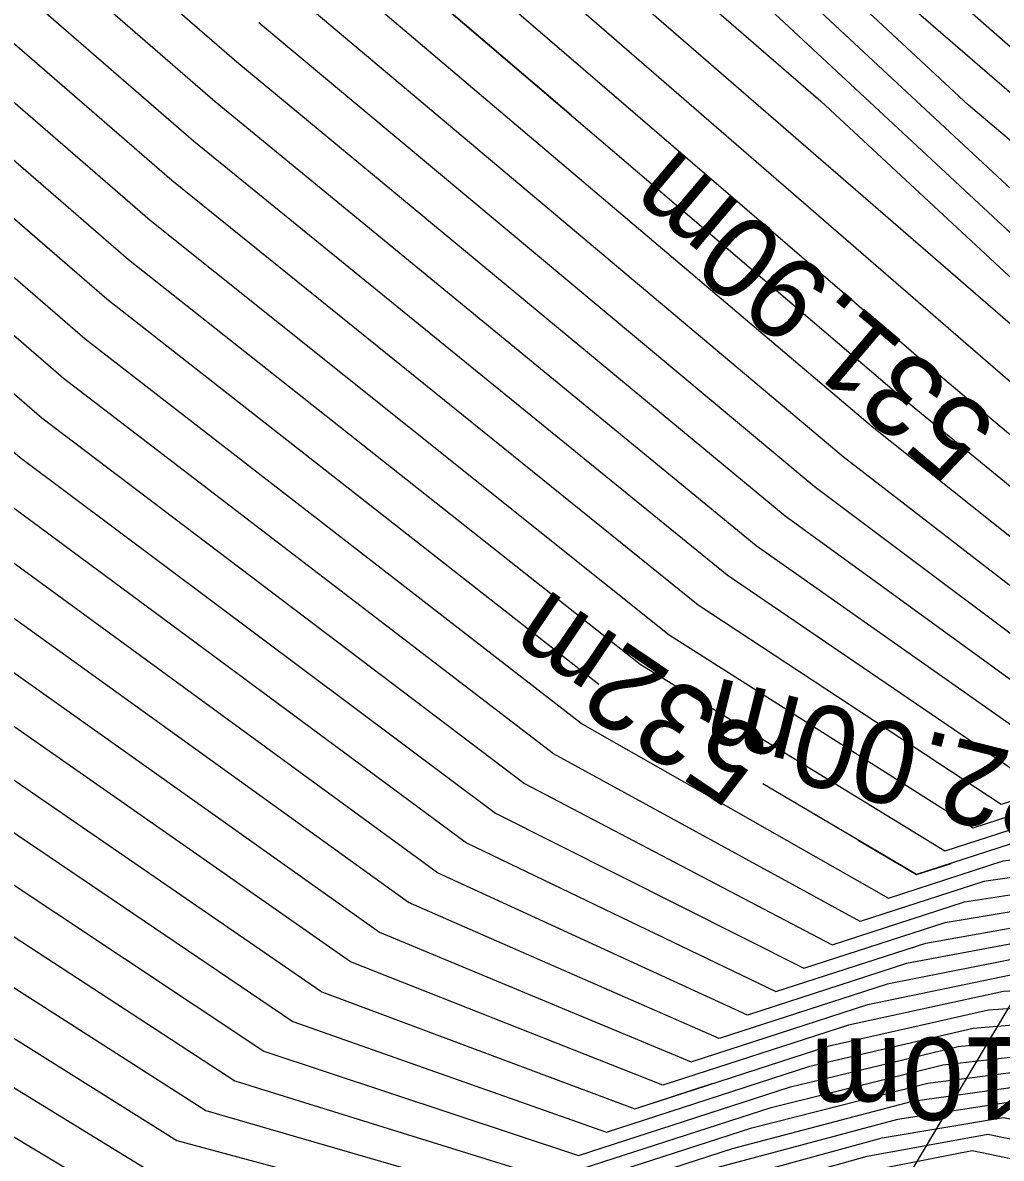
# Model space of a CAD drawing. Extents: x -866683 to -866410, y -1041951 to -1040252.
# Drawn here: x -866459.69 to -866456.13, y -1041911.908 to -1041907.774 of the extents above; entities that cross this region are included whole.
import ezdxf

# ---------------------------------------------------------------- set-up
doc = ezdxf.new("R2010")
doc.units = 0
for name, color, linetype in [('BREAKLINE', 7, 'Continuous'), ('V-HL', 7, 'Continuous'), ('V-POPIS', 7, 'Continuous'), ('V-VEDL', 7, 'Continuous'), ('V_po_cm', 7, 'Continuous')]:
    doc.layers.add(name, color=color, linetype=linetype)

msp = doc.modelspace()

# ---------------------------------------------------------------- linework, layer by layer
at = {"layer": 'BREAKLINE'}
msp.add_lwpolyline([(-866451.679, -1041950.508), (-866455.618, -1041922.473), (-866456.719, -1041912.396), (-866455.207, -1041909.853), (-866453.752, -1041908.342), (-866450, -1041907.538), (-866447.7, -1041908.076), (-866445.165, -1041909.459), (-866437.422, -1041915.176), (-866426.565, -1041925.108), (-866438.22, -1041915.868), (-866445.312, -1041910.554), (-866447.7, -1041908.076)], dxfattribs=at)
at = {"layer": 'V-HL'}
for points in [[(-866457.9912, -1041909.8721), (-866459.3844, -1041908.7805), (-866462.5795, -1041906.0104)], [(-866454.1336, -1041910.9392), (-866455.1554, -1041910.7301), (-866455.6246, -1041910.7021), (-866456.0521, -1041910.7506), (-866456.4378, -1041910.8756), (-866456.9974, -1041910.5447)]]:
    msp.add_lwpolyline(points, dxfattribs=at)
at = {"layer": 'V-VEDL'}
for points in [[(-866464.8326, -1041901.9329), (-866458.5952, -1041907.3405), (-866456.4946, -1041909.1361), (-866455.4121, -1041910.0234), (-866455.3478, -1041910.0026), (-866455.2712, -1041909.9956), (-866455.1823, -1041910.0025), (-866455.0809, -1041910.0232), (-866454.8963, -1041910.0431), (-866454.6284, -1041910.0621), (-866454.2772, -1041910.0802), (-866453.8271, -1041909.9814), (-866453.2781, -1041909.7659), (-866451.9822, -1041909.101)], [(-866464.1795, -1041906.7476), (-866460.1736, -1041910.2204), (-866458.6026, -1041911.3017), (-866457.4635, -1041911.7277), (-866456.7563, -1041911.4985), (-866456.1765, -1041911.3679), (-866455.724, -1041911.3359), (-866455.0738, -1041911.4689)]]:
    msp.add_lwpolyline(points, dxfattribs=at)
at = {"layer": 'V_po_cm'}
for points in [[(-866466.7257, -1041918.4088), (-866465.8144, -1041919.345), (-866465.3498, -1041920.4457), (-866464.8764, -1041922.179), (-866464.394, -1041924.5448), (-866464.1335, -1041925.3232), (-866464.0949, -1041924.5141), (-866464.2782, -1041922.1176), (-866464.4254, -1041920.041), (-866464.5366, -1041918.2845), (-866464.6118, -1041916.8481), (-866464.7452, -1041914.7264), (-866464.9369, -1041911.9194), (-866465.1867, -1041908.4272), (-866465.339, -1041906.0433), (-866465.3936, -1041904.7675), (-866465.3506, -1041904.6), (-866465.2837, -1041904.1035), (-866465.1928, -1041903.2783), (-866465.0781, -1041902.1241), (-866464.093, -1041902.1423), (-866462.2377, -1041903.3329), (-866456.7865, -1041908.0588)], [(-866466.7029, -1041918.503), (-866465.8023, -1041919.4282), (-866465.3386, -1041920.5388), (-866464.8614, -1041922.2974), (-866464.3707, -1041924.704), (-866464.1057, -1041925.4958), (-866464.0664, -1041924.6728), (-866464.2528, -1041922.2349), (-866464.4026, -1041920.1226), (-866464.5157, -1041918.3358), (-866464.5922, -1041916.8746), (-866464.7249, -1041914.7589), (-866464.9137, -1041911.9889), (-866465.1588, -1041908.5644), (-866465.3071, -1041906.2231), (-866465.3589, -1041904.965), (-866465.3141, -1041904.7902), (-866465.2465, -1041904.2953), (-866465.1564, -1041903.4805), (-866465.0435, -1041902.3456), (-866463.9756, -1041902.4496), (-866461.9527, -1041903.7924), (-866455.9968, -1041908.9559)], [(-866455.207, -1041909.853), (-866461.6676, -1041904.2519), (-866463.8582, -1041902.7568), (-866465.0089, -1041902.567), (-866465.1199, -1041903.6827), (-866465.2094, -1041904.4871), (-866465.2775, -1041904.9804), (-866465.3242, -1041905.1625), (-866465.2753, -1041906.4029), (-866465.1308, -1041908.7015), (-866464.8906, -1041912.0583), (-866464.7046, -1041914.7915), (-866464.5727, -1041916.9011), (-866464.4949, -1041918.3871), (-866464.3798, -1041920.2042), (-866464.2275, -1041922.3523), (-866464.0379, -1041924.8315), (-866464.0779, -1041925.6685), (-866464.3474, -1041924.8633), (-866464.8463, -1041922.4158), (-866465.3273, -1041920.6319), (-866465.7902, -1041919.5113), (-866466.6801, -1041918.5972)], [(-866452.7907, -1041908.7543), (-866453.4946, -1041909.1154), (-866453.8164, -1041909.2312), (-866454.1082, -1041909.2824), (-866454.3699, -1041909.2689), (-866455.2225, -1041908.6286), (-866456.6662, -1041907.3614), (-866460.7354, -1041903.5732)], [(-866452.7009, -1041908.7928), (-866453.4705, -1041909.1876), (-866453.8225, -1041909.3143), (-866454.1415, -1041909.3703), (-866454.4276, -1041909.3556), (-866455.1997, -1041908.8046), (-866456.4577, -1041907.7173), (-866459.9456, -1041904.4703)], [(-866457.6943, -1041908.1105), (-866458.5952, -1041907.3405), (-866460.8718, -1041905.3667)], [(-866452.6111, -1041908.8313), (-866453.4465, -1041909.2599), (-866453.8285, -1041909.3975), (-866454.1748, -1041909.4582), (-866454.4854, -1041909.4422), (-866455.1769, -1041908.9805), (-866456.2493, -1041908.0733), (-866459.1558, -1041905.3675)], [(-866461.8064, -1041905.4061), (-866458.9109, -1041907.9165), (-866456.9162, -1041909.5692), (-866455.8224, -1041910.3643), (-866455.6295, -1041910.3018), (-866455.3997, -1041910.2808), (-866455.1328, -1041910.3015), (-866454.5249, -1041910.4258)], [(-866461.8296, -1041905.5985), (-866458.9898, -1041908.0605), (-866457.0216, -1041909.6775), (-866455.925, -1041910.4495), (-866455.7, -1041910.3766), (-866455.4318, -1041910.3521), (-866455.1204, -1041910.3762), (-866454.4112, -1041910.5213)], [(-866454.2976, -1041910.6168), (-866455.108, -1041910.4509), (-866455.4639, -1041910.4235), (-866455.7704, -1041910.4514), (-866456.0276, -1041910.5347), (-866457.127, -1041909.7857), (-866459.0687, -1041908.2045), (-866461.8527, -1041905.7909)], [(-866454.1839, -1041910.7122), (-866455.0956, -1041910.5257), (-866455.496, -1041910.4948), (-866455.8408, -1041910.5262), (-866456.1301, -1041910.6199), (-866457.2324, -1041909.894), (-866459.1476, -1041908.3485), (-866461.8758, -1041905.9832)], [(-866461.899, -1041906.1756), (-866459.2266, -1041908.4925), (-866457.3378, -1041910.0023), (-866456.2327, -1041910.7051), (-866455.9112, -1041910.601), (-866455.5281, -1041910.5661), (-866455.0833, -1041910.6004), (-866454.0702, -1041910.8077)], [(-866452.5212, -1041908.8699), (-866453.4224, -1041909.3322), (-866453.8345, -1041909.4806), (-866454.2081, -1041909.5461), (-866454.5431, -1041909.5288), (-866455.154, -1041909.1565), (-866456.0408, -1041908.4292), (-866458.3661, -1041906.2646)], [(-866453.9556, -1041910.9838), (-866454.0116, -1041910.9187), (-866454.2068, -1041910.8609), (-866454.5691, -1041910.7779), (-866455.0986, -1041910.6695), (-866455.5694, -1041910.6355), (-866455.9817, -1041910.6758), (-866456.3353, -1041910.7903), (-866457.4432, -1041910.1106), (-866459.3055, -1041908.6365), (-866461.9221, -1041906.368)], [(-866461.9684, -1041906.7527), (-866459.4633, -1041908.9245), (-866457.654, -1041910.3271), (-866456.5404, -1041910.9608), (-866456.1225, -1041910.8254), (-866455.6798, -1041910.7687), (-866455.2123, -1041910.7907), (-866454.72, -1041910.8914), (-866454.3357, -1041911.0237), (-866454.0595, -1041911.1874), (-866453.7233, -1041911.5779)], [(-866453.0266, -1041913.3603), (-866454.2033, -1041911.9934), (-866454.7225, -1041911.5118), (-866455.1726, -1041911.2321), (-866455.5534, -1041911.1541), (-866456.0109, -1041911.1682), (-866456.5451, -1041911.2741), (-866457.1558, -1041911.4721), (-866458.2864, -1041910.9768), (-866459.9369, -1041909.7884), (-866462.1072, -1041907.9069), (-866463.5789, -1041906.9024)], [(-866453.6072, -1041911.875), (-866454.0835, -1041911.3217), (-866454.4002, -1041911.105), (-866454.7954, -1041910.9482), (-866455.2691, -1041910.8513), (-866455.735, -1041910.8352), (-866456.1929, -1041910.9002), (-866456.643, -1041911.046), (-866457.7594, -1041910.4354), (-866459.5423, -1041909.0685), (-866461.9915, -1041906.9451)], [(-866463.5642, -1041907.1206), (-866462.1303, -1041908.0993), (-866460.0158, -1041909.9324), (-866458.3918, -1041911.0851), (-866457.2584, -1041911.5573), (-866456.6155, -1041911.3489), (-866456.0661, -1041911.2347), (-866455.6103, -1041911.2147), (-866455.248, -1041911.2888), (-866454.787, -1041911.5932), (-866454.2273, -1041912.1278), (-866452.9104, -1041913.6573)], [(-866462.0146, -1041907.1374), (-866459.6212, -1041909.2125), (-866457.8648, -1041910.5437), (-866456.7455, -1041911.1312), (-866456.2634, -1041910.9749), (-866455.7902, -1041910.9018), (-866455.326, -1041910.9118), (-866454.8708, -1041911.005), (-866454.4647, -1041911.1864), (-866454.1075, -1041911.4561), (-866453.4911, -1041912.172)], [(-866457.5763, -1041907.1617), (-866455.8324, -1041908.7852), (-866455.1312, -1041909.3325), (-866454.6009, -1041909.6154), (-866454.2414, -1041909.634), (-866453.8405, -1041909.5637), (-866453.3984, -1041909.4045), (-866452.4314, -1041908.9084)], [(-866458.5162, -1041907.1965), (-866456.3892, -1041909.0278), (-866455.3096, -1041909.9382), (-866455.2774, -1041909.9278), (-866455.2391, -1041909.9243), (-866455.1946, -1041909.9277), (-866455.0933, -1041909.9485)], [(-866452.7943, -1041913.9544), (-866454.2513, -1041912.2621), (-866454.8515, -1041911.6746), (-866455.3234, -1041911.3456), (-866455.6671, -1041911.2753), (-866456.1213, -1041911.3013), (-866456.6859, -1041911.4237), (-866457.361, -1041911.6425), (-866458.4972, -1041911.1934), (-866460.0947, -1041910.0764), (-866462.1534, -1041908.2917), (-866463.5495, -1041907.3388)], [(-866462.0378, -1041907.3298), (-866459.7001, -1041909.3565), (-866457.9702, -1041910.652), (-866456.8481, -1041911.2164), (-866456.3338, -1041911.0497), (-866455.8454, -1041910.9684), (-866455.3829, -1041910.9724), (-866454.9463, -1041911.0617), (-866454.5291, -1041911.2677), (-866454.1314, -1041911.5904), (-866453.3749, -1041912.4691)], [(-866458.6741, -1041907.4845), (-866456.6, -1041909.2443), (-866455.5147, -1041910.1086), (-866455.4183, -1041910.0774), (-866455.3033, -1041910.0669), (-866455.1699, -1041910.0772), (-866454.866, -1041910.1394)], [(-866462.0609, -1041907.5222), (-866459.779, -1041909.5005), (-866458.0756, -1041910.7603), (-866456.9507, -1041911.3016), (-866456.4042, -1041911.1245), (-866455.9006, -1041911.035), (-866455.4397, -1041911.033), (-866455.0217, -1041911.1185), (-866454.5936, -1041911.3491), (-866454.1554, -1041911.7247), (-866453.2588, -1041912.7662)], [(-866457.5936, -1041910.1836), (-866459.3844, -1041908.7805), (-866460.802, -1041907.5515)], [(-866458.753, -1041907.6285), (-866456.7054, -1041909.3526), (-866455.6173, -1041910.1939), (-866455.4887, -1041910.1522), (-866455.3354, -1041910.1382), (-866455.1575, -1041910.152), (-866454.7523, -1041910.2349)], [(-866464.0149, -1041919.5667), (-866464.1225, -1041917.511), (-866464.2372, -1041915.5405), (-866464.3589, -1041913.6552), (-866464.4877, -1041911.8549), (-866464.5437, -1041910.5382), (-866464.5268, -1041909.705), (-866464.4371, -1041909.3554), (-866464.355, -1041908.8981), (-866464.2806, -1041908.3332), (-866464.2137, -1041907.6608), (-866463.5201, -1041907.7752), (-866462.1997, -1041908.6764), (-866460.2526, -1041910.3644), (-866458.708, -1041911.41), (-866457.5661, -1041911.8129), (-866456.8268, -1041911.5733), (-866456.2317, -1041911.4345), (-866455.7809, -1041911.3965), (-866455.4743, -1041911.4592), (-866454.9804, -1041911.8373), (-866454.2992, -1041912.5308), (-866452.5621, -1041914.5485)], [(-866453.1427, -1041913.0632), (-866454.1794, -1041911.8591), (-866454.6581, -1041911.4305), (-866455.0971, -1041911.1753), (-866455.4966, -1041911.0936), (-866455.9557, -1041911.1016), (-866456.4746, -1041911.1993), (-866457.0533, -1041911.3868), (-866458.181, -1041910.8685), (-866459.8579, -1041909.6444), (-866462.084, -1041907.7146)], [(-866458.8319, -1041907.7725), (-866456.8108, -1041909.4609), (-866455.7198, -1041910.2791), (-866455.5591, -1041910.227), (-866455.3675, -1041910.2095), (-866455.1451, -1041910.2267), (-866454.6386, -1041910.3304)], [(-866463.994, -1041919.6179), (-866464.1029, -1041917.5376), (-866464.2169, -1041915.5731), (-866464.3358, -1041913.7246), (-866464.4598, -1041911.992), (-866464.5119, -1041910.718), (-866464.4922, -1041909.9025), (-866464.4006, -1041909.5456), (-866464.3179, -1041909.0899), (-866464.2441, -1041908.5354), (-866464.1791, -1041907.8823), (-866463.5054, -1041907.9934), (-866462.2228, -1041908.8688), (-866460.3315, -1041910.5084), (-866458.8134, -1041911.5182), (-866457.6687, -1041911.8981), (-866456.8972, -1041911.6481), (-866456.2869, -1041911.5011), (-866455.8377, -1041911.457), (-866455.5498, -1041911.516), (-866455.0449, -1041911.9186), (-866454.3232, -1041912.6651), (-866452.446, -1041914.8455)], [(-866456.7865, -1041908.0588), (-866455.6239, -1041909.1411), (-866455.1084, -1041909.5085), (-866454.6586, -1041909.7021), (-866454.2747, -1041909.7219), (-866453.8466, -1041909.6468), (-866453.3743, -1041909.4768), (-866452.3416, -1041908.9469)], [(-866463.9732, -1041919.6692), (-866464.0834, -1041917.5641), (-866464.1965, -1041915.6057), (-866464.3127, -1041913.794), (-866464.4318, -1041912.1292), (-866464.4801, -1041910.8978), (-866464.4575, -1041910.1), (-866464.364, -1041909.7358), (-866464.2807, -1041909.2817), (-866464.2076, -1041908.7376), (-866464.1445, -1041908.1037), (-866463.4907, -1041908.2115), (-866462.2459, -1041909.0611), (-866460.4104, -1041910.6524), (-866458.9188, -1041911.6265), (-866457.7712, -1041911.9833), (-866456.9676, -1041911.7229), (-866456.342, -1041911.5677), (-866455.8946, -1041911.5176), (-866455.6252, -1041911.5727), (-866455.1094, -1041912), (-866454.3471, -1041912.7994), (-866452.3298, -1041915.1426)], [(-866463.9523, -1041919.7205), (-866464.0638, -1041917.5906), (-866464.1762, -1041915.6382), (-866464.2896, -1041913.8635), (-866464.4038, -1041912.2663), (-866464.4483, -1041911.0776), (-866464.4228, -1041910.2975), (-866464.3275, -1041909.926), (-866464.2436, -1041909.4735), (-866464.1711, -1041908.9398), (-866464.11, -1041908.3252), (-866463.476, -1041908.4297), (-866462.2691, -1041909.2535), (-866460.4893, -1041910.7964), (-866459.0242, -1041911.7348), (-866457.8738, -1041912.0686), (-866457.038, -1041911.7977), (-866456.3972, -1041911.6343), (-866455.9514, -1041911.5782), (-866455.7006, -1041911.6295), (-866455.1738, -1041912.0814), (-866454.3711, -1041912.9338), (-866452.2137, -1041915.4397)], [(-866463.9314, -1041919.7718), (-866464.0442, -1041917.6171), (-866464.1559, -1041915.6708), (-866464.2665, -1041913.9329), (-866464.3759, -1041912.4034), (-866464.4164, -1041911.2574), (-866464.3881, -1041910.495), (-866464.291, -1041910.1162), (-866464.2065, -1041909.6652), (-866464.1346, -1041909.142), (-866464.0754, -1041908.5467), (-866463.4613, -1041908.6479), (-866462.2922, -1041909.4459), (-866460.5683, -1041910.9404), (-866459.1296, -1041911.8431), (-866457.9764, -1041912.1538), (-866457.1084, -1041911.8725), (-866456.4524, -1041911.7008), (-866456.0083, -1041911.6388), (-866455.7761, -1041911.6863), (-866455.2383, -1041912.1627), (-866454.3951, -1041913.0681), (-866452.0976, -1041915.7367)], [(-866451.9815, -1041916.0338), (-866454.4191, -1041913.2024), (-866455.3028, -1041912.2441), (-866455.8515, -1041911.7431), (-866456.0651, -1041911.6993), (-866456.5076, -1041911.7674), (-866457.1789, -1041911.9473), (-866458.0789, -1041912.239), (-866459.2351, -1041911.9514), (-866460.6472, -1041911.0844), (-866462.3153, -1041909.6382), (-866463.4466, -1041908.8661), (-866464.0408, -1041908.7681), (-866464.0981, -1041909.3442), (-866464.1693, -1041909.857), (-866464.2544, -1041910.3064), (-866464.3535, -1041910.6925), (-866464.3846, -1041911.4372), (-866464.3479, -1041912.5405), (-866464.2433, -1041914.0023), (-866464.1356, -1041915.7034), (-866464.0247, -1041917.6436), (-866463.9105, -1041919.8231)], [(-866463.8897, -1041919.8744), (-866464.0051, -1041917.6701), (-866464.1153, -1041915.7359), (-866464.2202, -1041914.0717), (-866464.32, -1041912.6776), (-866464.3528, -1041911.617), (-866464.3188, -1041910.89), (-866464.2179, -1041910.4967), (-866464.1322, -1041910.0488), (-866464.0616, -1041909.5464), (-866464.0062, -1041908.9896), (-866463.4319, -1041909.0843), (-866462.3385, -1041909.8306), (-866460.7261, -1041911.2284), (-866459.3405, -1041912.0596), (-866458.1815, -1041912.3242), (-866457.2493, -1041912.0221), (-866456.5628, -1041911.834), (-866456.122, -1041911.7599), (-866455.9269, -1041911.7998), (-866455.3673, -1041912.3255), (-866454.443, -1041913.3368), (-866451.8653, -1041916.3308)], [(-866463.8688, -1041919.9257), (-866463.9855, -1041917.6967), (-866464.0949, -1041915.7685), (-866464.1971, -1041914.1412), (-866464.292, -1041912.8147), (-866464.321, -1041911.7968), (-866464.2841, -1041911.0875), (-866464.1814, -1041910.6869), (-866464.095, -1041910.2406), (-866464.0251, -1041909.7486), (-866463.9717, -1041909.2111), (-866463.4172, -1041909.3025), (-866462.3616, -1041910.023), (-866460.805, -1041911.3724), (-866459.4459, -1041912.1679), (-866458.2841, -1041912.4094), (-866457.3197, -1041912.0969), (-866456.618, -1041911.9006), (-866456.1789, -1041911.8205), (-866456.0024, -1041911.8566), (-866455.4317, -1041912.4068), (-866454.467, -1041913.4711), (-866451.7492, -1041916.6279)], [(-866451.6331, -1041916.9249), (-866454.491, -1041913.6054), (-866455.4962, -1041912.4882), (-866456.0778, -1041911.9134), (-866456.2357, -1041911.8811), (-866456.6732, -1041911.9672), (-866457.3901, -1041912.1717), (-866458.3867, -1041912.4946), (-866459.5513, -1041912.2762), (-866460.884, -1041911.5164), (-866462.3847, -1041910.2153), (-866463.4024, -1041909.5207), (-866463.9371, -1041909.4325), (-866463.9886, -1041909.9508), (-866464.0579, -1041910.4324), (-866464.1448, -1041910.8771), (-866464.2495, -1041911.285), (-866464.2892, -1041911.9766), (-866464.264, -1041912.9518), (-866464.174, -1041914.2106), (-866464.0746, -1041915.8011), (-866463.9659, -1041917.7232), (-866463.8479, -1041919.9769)], [(-866460.7343, -1041909.7344), (-866460.1736, -1041910.2204), (-866458.6026, -1041911.3017), (-866457.4635, -1041911.7277), (-866457.1815, -1041911.6363)], [(-866456.6507, -1041910.7497), (-866456.4378, -1041910.8756), (-866456.312, -1041910.8348)]]:
    msp.add_lwpolyline(points, dxfattribs=at)

# ---------------------------------------------------------------- texts
at = {"layer": 'V-POPIS'}
msp.add_text('532m', height=0.3, rotation=145.9081, dxfattribs=at).set_placement((-866456.9531, -1041910.3937))
at = {"layer": 'V_po_cm'}
for s, rotation, p in [('531.90m', 139.7692, (-866456.1323, -1041909.2355)), ('532.00m', 165.9019, (-866455.6511, -1041910.5368)), ('532.10m', 180.4477, (-866455.2638, -1041911.4604))]:
    msp.add_text(s, height=0.3, rotation=rotation, dxfattribs=at).set_placement(p)

doc.saveas('drawing.dxf')
